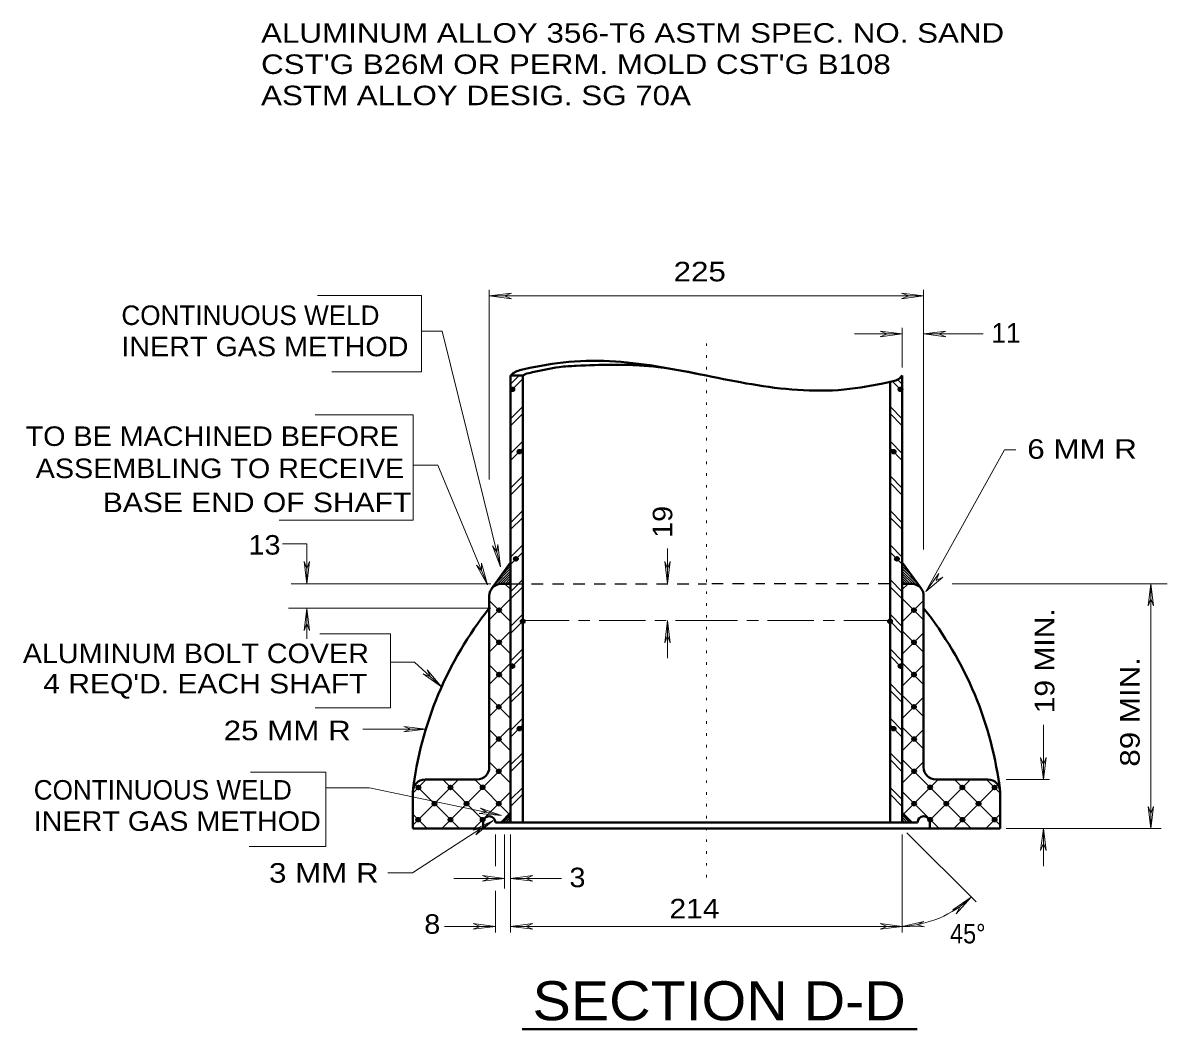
# Model space of a CAD drawing. Extents: x 312583 to 312854, y 144418 to 144597.
# Drawn here: x 312764.39 to 312808.95, y 144460.51 to 144499.71 of the extents above; entities that cross this region are included whole.
import ezdxf
from ezdxf.enums import TextEntityAlignment as Align

# ---------------------------------------------------------------- set-up
doc = ezdxf.new("R2010")
doc.units = 0
doc.header["$LTSCALE"] = 0.3
doc.header["$PDMODE"] = 32
doc.header["$PDSIZE"] = 0.15
for name, pattern in [('DOTTED', [1.5, 0.3, -1.2]), ('LONG_DASH_SHORT_DASH', [9.9, 6, -1.2, 1.5, -1.2]), ('SHORT_DASHED', [2.7, 1.5, -1.2])]:
    doc.linetypes.add(name, pattern=pattern)
doc.layers.add('1', color=7, linetype='Continuous', lineweight=35)

msp = doc.modelspace()

# ---------------------------------------------------------------- linework, layer by layer
at = {"layer": '1', "lineweight": 13}
for p, q in [((312775.8618, 144489.093), (312779.9183, 144489.093)), ((312779.9183, 144486.1193), (312779.9183, 144489.093)), ((312782.5566, 144481.9255), (312782.5566, 144489.3065)), ((312782.5566, 144489.0702), (312783.4182, 144489.1769)), ((312782.5566, 144489.0702), (312799.4688, 144489.0702)), ((312782.5566, 144489.0702), (312783.4182, 144488.9634)), ((312783.4182, 144489.1769), (312783.1437, 144489.0702)), ((312783.4182, 144488.9634), (312783.1437, 144489.0702)), ((312798.6148, 144489.1769), (312798.8893, 144489.0702)), ((312799.4688, 144489.0702), (312798.6148, 144489.1769)), ((312798.6148, 144488.9634), (312798.8893, 144489.0702)), ((312799.4688, 144489.0702), (312798.6148, 144488.9634)), ((312799.4688, 144479.1958), (312799.4688, 144489.3065)), ((312779.9183, 144487.6976), (312780.7189, 144487.6976)), ((312780.7189, 144487.6976), (312782.9912, 144478.5248)), ((312798.6377, 144487.5909), (312796.7848, 144487.5909)), ((312797.776, 144487.6976), (312798.0506, 144487.5909)), ((312798.6377, 144487.5909), (312797.776, 144487.6976)), ((312797.776, 144487.4842), (312798.0506, 144487.5909)), ((312798.6377, 144487.5909), (312797.776, 144487.4842)), ((312798.6377, 144486.2794), (312798.6377, 144487.8273)), ((312799.4764, 144487.5909), (312800.338, 144487.6976)), ((312799.4764, 144487.5909), (312801.7944, 144487.5909)), ((312799.4764, 144487.5909), (312800.338, 144487.4842)), ((312800.338, 144487.6976), (312800.0636, 144487.5909)), ((312800.338, 144487.4842), (312800.0636, 144487.5909)), ((312776.426, 144486.1193), (312779.9183, 144486.1193)), ((312783.3877, 144485.6313), (312783.7232, 144485.9668)), ((312783.3877, 144485.3644), (312783.868, 144485.8372)), ((312798.6377, 144485.6313), (312798.4394, 144485.8295)), ((312798.6377, 144485.3644), (312798.2717, 144485.7304)), ((312775.7703, 144484.4418), (312779.5904, 144484.4418)), ((312779.5904, 144480.3395), (312779.5904, 144484.4418)), ((312783.3877, 144484.2816), (312783.868, 144484.762)), ((312783.3877, 144484.0148), (312783.868, 144484.4875)), ((312798.6377, 144484.2816), (312798.1649, 144484.762)), ((312798.6377, 144484.0148), (312798.1649, 144484.4875)), ((312783.3877, 144482.932), (312783.868, 144483.4124)), ((312783.3877, 144482.6652), (312783.868, 144483.1455)), ((312798.6377, 144482.932), (312798.1649, 144483.4124)), ((312798.6377, 144482.6652), (312798.1649, 144483.1455)), ((312799.5527, 144477.5564), (312802.6215, 144483.0727)), ((312802.6215, 144483.0727), (312803.0638, 144483.0727)), ((312779.5904, 144482.4822), (312780.5588, 144482.4822)), ((312780.5588, 144482.4822), (312782.4803, 144477.8233)), ((312783.3877, 144481.59), (312783.868, 144482.0628)), ((312783.3877, 144481.3155), (312783.868, 144481.7959)), ((312798.6377, 144481.59), (312798.1649, 144482.0628)), ((312798.6377, 144481.3155), (312798.1649, 144481.7959)), ((312783.3877, 144480.2404), (312783.868, 144480.7208)), ((312783.3877, 144479.9735), (312783.868, 144480.4463)), ((312798.6377, 144480.2404), (312798.1649, 144480.7208)), ((312798.6377, 144479.9735), (312798.1649, 144480.4463)), ((312774.3749, 144480.3395), (312779.5904, 144480.3395)), ((312774.4969, 144479.4169), (312775.45, 144479.4169)), ((312775.45, 144477.8614), (312775.45, 144479.4169)), ((312782.6786, 144479.333), (312782.8463, 144479.0966)), ((312782.9912, 144478.5248), (312782.6786, 144479.333)), ((312782.8844, 144479.3864), (312782.8463, 144479.0966)), ((312782.9912, 144478.5248), (312782.8844, 144479.3864)), ((312783.3877, 144478.8908), (312783.868, 144479.3712)), ((312783.3877, 144478.6163), (312783.868, 144479.0966)), ((312789.4953, 144477.8614), (312789.4953, 144479.2339)), ((312798.6377, 144478.8908), (312798.1649, 144479.3712)), ((312798.6453, 144478.6163), (312798.1649, 144479.0966)), ((312775.3433, 144478.723), (312775.45, 144478.4485)), ((312775.45, 144477.8614), (312775.3433, 144478.723)), ((312775.5568, 144478.723), (312775.45, 144478.4485)), ((312775.45, 144477.8614), (312775.5568, 144478.723)), ((312782.2516, 144478.662), (312782.2516, 144478.3723)), ((312782.4803, 144477.8233), (312782.2516, 144478.662)), ((312789.3886, 144478.723), (312789.4953, 144478.4485)), ((312789.4953, 144477.8614), (312789.3886, 144478.723)), ((312789.602, 144478.723), (312789.4953, 144478.4485)), ((312789.4953, 144477.8614), (312789.602, 144478.723)), ((312782.0533, 144478.5858), (312782.2516, 144478.3723)), ((312782.4803, 144477.8233), (312782.0533, 144478.5858)), ((312799.5527, 144477.5564), (312800.0636, 144478.2579)), ((312800.0636, 144478.2579), (312799.9568, 144477.9834)), ((312782.6176, 144477.8614), (312774.84, 144477.8614)), ((312783.3953, 144477.6326), (312783.1666, 144477.8614)), ((312783.3877, 144477.5412), (312783.868, 144478.0215)), ((312798.6377, 144477.5412), (312798.1649, 144478.0215)), ((312798.6377, 144477.6326), (312798.8664, 144477.8614)), ((312799.5527, 144477.5564), (312800.216, 144478.113)), ((312800.216, 144478.113), (312799.9568, 144477.9834)), ((312808.9543, 144477.8614), (312800.582, 144477.8614)), ((312808.3214, 144477.8614), (312808.2147, 144476.9998)), ((312808.3214, 144468.3302), (312808.3214, 144477.8614)), ((312808.3214, 144477.8614), (312808.4282, 144476.9998)), ((312783.3877, 144477.2743), (312783.868, 144477.747)), ((312798.6377, 144477.2743), (312798.1649, 144477.747)), ((312782.6176, 144476.9083), (312774.7409, 144476.9083)), ((312775.45, 144476.9006), (312775.3433, 144476.039)), ((312775.45, 144475.7188), (312775.45, 144476.9006)), ((312775.45, 144476.9006), (312775.5568, 144476.039)), ((312782.5566, 144476.4508), (312783.3953, 144477.2895)), ((312783.3953, 144476.3745), (312782.5566, 144477.2133)), ((312799.4688, 144476.4508), (312798.6377, 144477.2895)), ((312798.6377, 144476.3745), (312799.4688, 144477.2133)), ((312808.2147, 144476.9998), (312808.3214, 144477.2743)), ((312808.4282, 144476.9998), (312808.3214, 144477.2743)), ((312783.3877, 144476.1915), (312783.868, 144476.6719)), ((312789.4953, 144476.4355), (312789.3886, 144475.5663)), ((312789.4953, 144474.9639), (312789.4953, 144476.4355)), ((312789.4953, 144476.4355), (312789.602, 144475.5663)), ((312798.6377, 144476.1915), (312798.1649, 144476.6719)), ((312775.3433, 144476.039), (312775.45, 144476.3135)), ((312775.5568, 144476.039), (312775.45, 144476.3135)), ((312782.5566, 144475.2003), (312783.3953, 144476.0314)), ((312783.3877, 144475.9246), (312783.868, 144476.405)), ((312798.6377, 144475.9246), (312798.1649, 144476.405)), ((312799.4688, 144475.2003), (312798.6377, 144476.0314)), ((312775.9533, 144475.917), (312778.7059, 144475.917)), ((312783.3953, 144475.124), (312782.5566, 144475.9552)), ((312789.3886, 144475.5663), (312789.4953, 144475.8408)), ((312789.602, 144475.5663), (312789.4953, 144475.8408)), ((312798.6377, 144475.124), (312799.4688, 144475.9552)), ((312783.3877, 144474.8495), (312783.868, 144475.3223)), ((312798.6377, 144474.8495), (312798.1649, 144475.3223)), ((312782.5566, 144473.9422), (312783.3953, 144474.7809)), ((312783.3953, 144473.8659), (312782.5566, 144474.697)), ((312783.3877, 144474.575), (312783.868, 144475.0554)), ((312798.6377, 144474.575), (312798.1649, 144475.0554)), ((312799.4688, 144473.9422), (312798.6377, 144474.7809)), ((312798.6377, 144473.8659), (312799.4688, 144474.697)), ((312779.9869, 144474.3463), (312780.2614, 144474.2395)), ((312780.696, 144473.8506), (312779.9869, 144474.3463)), ((312780.1318, 144474.5064), (312780.2614, 144474.2395)), ((312780.696, 144473.8506), (312780.1318, 144474.5064)), ((312783.3953, 144473.4999), (312783.868, 144473.9803)), ((312798.6377, 144473.4999), (312798.1649, 144473.9803)), ((312782.5566, 144472.6916), (312783.3953, 144473.5228)), ((312783.3877, 144472.6078), (312782.5566, 144473.4465)), ((312783.3877, 144473.233), (312783.868, 144473.7058)), ((312798.6377, 144473.233), (312798.1649, 144473.7058)), ((312799.4688, 144472.6916), (312798.6377, 144473.5228)), ((312798.6377, 144472.6078), (312799.4688, 144473.4465)), ((312783.3877, 144472.1503), (312783.868, 144472.6306)), ((312798.6377, 144472.1503), (312798.1649, 144472.6306)), ((312777.6338, 144472.196), (312780.086, 144472.196)), ((312779.2244, 144472.3028), (312779.4989, 144472.196)), ((312780.086, 144472.196), (312779.2244, 144472.3028)), ((312779.2244, 144472.0893), (312779.4989, 144472.196)), ((312780.086, 144472.196), (312779.2244, 144472.0893)), ((312782.5566, 144471.4335), (312783.3877, 144472.2723)), ((312783.3877, 144471.3573), (312782.5566, 144472.1884)), ((312783.3877, 144471.8834), (312783.868, 144472.3638)), ((312798.6377, 144471.8834), (312798.1649, 144472.3638)), ((312799.4688, 144471.4335), (312798.6377, 144472.2723)), ((312798.6377, 144471.3573), (312799.4688, 144472.1884)), ((312804.1353, 144470.2364), (312804.1353, 144472.3615)), ((312783.3877, 144470.8083), (312783.868, 144471.281)), ((312798.6377, 144470.8083), (312798.1649, 144471.281)), ((312804.0286, 144471.098), (312804.1353, 144470.8235)), ((312804.1353, 144470.2364), (312804.0286, 144471.098)), ((312804.242, 144471.098), (312804.1353, 144470.8235)), ((312804.1353, 144470.2364), (312804.242, 144471.098)), ((312780.7037, 144468.3302), (312783.3953, 144471.0218)), ((312783.3877, 144470.0992), (312782.5566, 144470.9303)), ((312783.3877, 144470.5338), (312783.868, 144471.0142)), ((312798.6377, 144470.5338), (312798.1649, 144471.0142)), ((312801.3293, 144468.3302), (312798.6377, 144471.0218)), ((312798.6377, 144470.0992), (312799.4688, 144470.9303)), ((312773.254, 144470.5185), (312776.1897, 144470.5185)), ((312776.1897, 144467.6286), (312776.1897, 144470.5185)), ((312779.5752, 144468.4598), (312781.3518, 144470.2364)), ((312779.5752, 144469.7103), (312780.1013, 144470.2364)), ((312782.3278, 144468.6428), (312780.7418, 144470.2364)), ((312783.3877, 144468.841), (312781.9923, 144470.2364)), ((312798.6377, 144468.841), (312800.033, 144470.2364)), ((312799.6976, 144468.6428), (312801.2912, 144470.2364)), ((312802.4502, 144468.4598), (312800.6736, 144470.2364)), ((312802.4502, 144469.7103), (312801.924, 144470.2364)), ((312802.6866, 144470.2364), (312804.3717, 144470.2364)), ((312776.1897, 144469.9085), (312777.89, 144469.9085)), ((312777.89, 144469.9085), (312783.0369, 144468.841)), ((312781.3899, 144468.3302), (312779.5752, 144470.1373)), ((312781.9542, 144468.3302), (312783.3953, 144469.7636)), ((312783.3877, 144469.4586), (312783.868, 144469.9314)), ((312798.6377, 144469.4586), (312798.1649, 144469.9314)), ((312800.0712, 144468.3302), (312798.6377, 144469.7636)), ((312800.643, 144468.3302), (312802.4502, 144470.1373)), ((312783.3877, 144469.1842), (312783.868, 144469.6645)), ((312798.6377, 144469.1842), (312798.1649, 144469.6645)), ((312780.1318, 144468.3302), (312779.5752, 144468.8868)), ((312782.1677, 144468.9096), (312782.4574, 144468.963)), ((312783.0369, 144468.841), (312782.1677, 144468.9096)), ((312782.2134, 144469.1155), (312782.4574, 144468.963)), ((312783.0369, 144468.841), (312782.2134, 144469.1155)), ((312801.8936, 144468.3302), (312802.4502, 144468.8868)), ((312808.2147, 144469.1918), (312808.3214, 144468.9173)), ((312808.3214, 144468.3302), (312808.2147, 144469.1918)), ((312808.4282, 144469.1918), (312808.3214, 144468.9173)), ((312808.3214, 144468.3302), (312808.4282, 144469.1918)), ((312782.709, 144468.6428), (312779.5599, 144466.6069)), ((312782.709, 144468.6428), (312781.9237, 144468.2692)), ((312782.709, 144468.6428), (312782.038, 144468.0862)), ((312783.8528, 144468.5665), (312783.868, 144468.5818)), ((312798.1802, 144468.5665), (312798.1649, 144468.5818)), ((312781.9237, 144468.2692), (312782.2134, 144468.3225)), ((312782.038, 144468.0862), (312782.2134, 144468.3225)), ((312782.7929, 144468.0938), (312782.7929, 144466.8585)), ((312783.1513, 144468.0938), (312783.1513, 144465.9969)), ((312783.3877, 144468.0938), (312783.3877, 144464.2813)), ((312798.6377, 144468.0938), (312798.6377, 144464.2813)), ((312798.813, 144468.1624), (312801.5123, 144465.4708)), ((312802.6866, 144468.3302), (312808.7256, 144468.3302)), ((312804.1353, 144468.3302), (312804.0286, 144467.4685)), ((312804.1353, 144466.8585), (312804.1353, 144468.3302)), ((312804.1353, 144468.3302), (312804.242, 144467.4685)), ((312773.2083, 144467.6286), (312776.1897, 144467.6286)), ((312804.0286, 144467.4685), (312804.1353, 144467.743)), ((312804.242, 144467.4685), (312804.1353, 144467.743)), ((312778.6068, 144466.6069), (312779.5599, 144466.6069)), ((312783.1513, 144466.3858), (312781.1764, 144466.3858)), ((312782.2897, 144466.4925), (312782.5642, 144466.3858)), ((312783.1513, 144466.3858), (312782.2897, 144466.4925)), ((312782.2897, 144466.279), (312782.5642, 144466.3858)), ((312783.1513, 144466.3858), (312782.2897, 144466.279)), ((312783.3877, 144466.3858), (312784.2493, 144466.4925)), ((312785.3626, 144466.3858), (312783.3877, 144466.3858)), ((312783.3877, 144466.3858), (312784.2493, 144466.279)), ((312784.2493, 144466.4925), (312783.9748, 144466.3858)), ((312784.2493, 144466.279), (312783.9748, 144466.3858)), ((312782.7929, 144465.9054), (312782.7929, 144464.2813)), ((312801.3293, 144465.6538), (312800.6049, 144465.1658)), ((312801.3293, 144465.6538), (312800.7422, 144465.0056)), ((312800.6049, 144465.1658), (312800.887, 144465.2649)), ((312800.7422, 144465.0056), (312800.887, 144465.2649)), ((312782.7929, 144464.5176), (312780.818, 144464.5176)), ((312781.9313, 144464.6244), (312782.2058, 144464.5176)), ((312782.7929, 144464.5176), (312781.9313, 144464.6244)), ((312781.9313, 144464.4109), (312782.2058, 144464.5176)), ((312782.7929, 144464.5176), (312781.9313, 144464.4109)), ((312783.3877, 144464.5176), (312784.2493, 144464.6244)), ((312783.3877, 144464.5176), (312798.6377, 144464.5176)), ((312783.3877, 144464.5176), (312784.2493, 144464.4109)), ((312784.2493, 144464.6244), (312783.9748, 144464.5176)), ((312784.2493, 144464.4109), (312783.9748, 144464.5176)), ((312797.776, 144464.6244), (312798.0506, 144464.5176)), ((312798.6377, 144464.5176), (312797.776, 144464.6244)), ((312797.776, 144464.4109), (312798.0506, 144464.5176)), ((312798.6377, 144464.5176), (312797.776, 144464.4109)), ((312798.6377, 144464.5176), (312799.484, 144464.7083)), ((312798.6377, 144464.5176), (312799.5069, 144464.4948)), ((312799.484, 144464.7083), (312799.2248, 144464.571)), ((312799.5069, 144464.4948), (312799.2248, 144464.571))]:
    msp.add_line(p, q, dxfattribs=at)
at = {"layer": '1', "linetype": 'DOTTED', "lineweight": 13}
msp.add_line((312791.0127, 144466.4239), (312791.0127, 144487.2706), dxfattribs=at)
at = {"layer": '1', "lineweight": 40}
for p, q in [((312783.3877, 144485.9668), (312783.3877, 144468.5665)), ((312783.868, 144485.9668), (312783.3877, 144485.9668)), ((312783.868, 144485.9668), (312783.868, 144468.5665)), ((312798.6377, 144485.9668), (312798.6377, 144468.5665)), ((312798.1649, 144485.7152), (312798.1649, 144468.5665)), ((312783.3877, 144478.6925), (312782.648, 144477.6632)), ((312798.6377, 144478.6925), (312799.3849, 144477.6632)), ((312783.0293, 144477.8614), (312783.3953, 144477.8614)), ((312798.996, 144477.8614), (312798.6377, 144477.8614)), ((312782.5566, 144477.381), (312782.5566, 144470.7168)), ((312799.4688, 144477.381), (312799.4688, 144470.7168)), ((312780.0556, 144470.2364), (312782.0838, 144470.2364)), ((312801.9774, 144470.2364), (312799.9492, 144470.2364)), ((312779.5752, 144469.756), (312779.5752, 144468.3302)), ((312802.4502, 144469.756), (312802.4502, 144468.3302)), ((312783.0217, 144468.5665), (312783.3877, 144468.9325)), ((312799.0113, 144468.5665), (312798.6377, 144468.9325)), ((312782.3202, 144468.5665), (312782.3202, 144468.3302)), ((312782.7929, 144468.5665), (312791.0127, 144468.5665)), ((312799.2324, 144468.5665), (312791.0127, 144468.5665)), ((312799.7128, 144468.5665), (312799.7128, 144468.3302)), ((312779.5752, 144468.3302), (312791.0127, 144468.3302)), ((312802.4502, 144468.3302), (312791.0127, 144468.3302)), ((312783.8353, 144460.5145), (312799.2201, 144460.5145))]:
    msp.add_line(p, q, dxfattribs=at)
at = {"layer": '1', "lineweight": 25}
for p, q in [((312783.258, 144478.5095), (312783.3877, 144478.6468)), ((312798.7749, 144478.5095), (312798.6377, 144478.6468)), ((312782.77, 144477.8385), (312783.3877, 144478.4562)), ((312782.8768, 144477.8462), (312783.3877, 144478.357)), ((312782.9759, 144477.8538), (312783.3877, 144478.2655)), ((312783.014, 144478.174), (312783.3877, 144478.5476)), ((312799.0113, 144478.174), (312798.6377, 144478.5476)), ((312799.2553, 144477.8385), (312798.6377, 144478.4562)), ((312799.1562, 144477.8462), (312798.6377, 144478.357)), ((312799.0494, 144477.8538), (312798.6377, 144478.2655)), ((312783.075, 144477.8614), (312783.3877, 144478.174)), ((312783.1742, 144477.8614), (312783.3877, 144478.0825)), ((312783.2657, 144477.8614), (312783.3877, 144477.9834)), ((312783.3648, 144477.8614), (312783.3877, 144477.8919)), ((312798.9503, 144477.8614), (312798.6377, 144478.174)), ((312798.8588, 144477.8614), (312798.6377, 144478.0825)), ((312798.7597, 144477.8614), (312798.6377, 144477.9834)), ((312798.6682, 144477.8614), (312798.6377, 144477.8919)), ((312783.1056, 144468.5665), (312783.3877, 144468.8563)), ((312798.9274, 144468.5665), (312798.6377, 144468.8563)), ((312783.197, 144468.5665), (312783.3877, 144468.7648)), ((312783.2886, 144468.5665), (312783.3877, 144468.6656)), ((312783.3877, 144468.5665), (312783.3877, 144468.5742)), ((312798.8283, 144468.5665), (312798.6377, 144468.7648)), ((312798.7368, 144468.5665), (312798.6377, 144468.6656)), ((312798.6453, 144468.5665), (312798.6377, 144468.5742))]:
    msp.add_line(p, q, dxfattribs=at)
at = {"layer": '1', "linetype": 'SHORT_DASHED', "lineweight": 25}
for p in [(312783.3953, 144477.8614), (312798.1497, 144477.8614)]:
    msp.add_line(p, (312791.0127, 144477.8614), dxfattribs=at)
at = {"layer": '1', "linetype": 'LONG_DASH_SHORT_DASH', "lineweight": 13}
for p in [(312783.868, 144476.4355), (312798.1649, 144476.4355)]:
    msp.add_line(p, (312791.0127, 144476.4355), dxfattribs=at)
at = {"layer": '1', "lineweight": 13}
for points in [[(312775.7703, 144473.0272), (312778.7059, 144473.0272), (312778.7059, 144475.917)], [(312778.7059, 144474.8038), (312779.6438, 144474.8038), (312780.696, 144473.8506)]]:
    msp.add_lwpolyline(points, dxfattribs=at)
at = {"layer": '1', "lineweight": 40}
for centre, radius, start, end in [((312783.0331, 144477.3848), 0.4766, 90, 180), ((312798.9961, 144477.3848), 0.4766, 0, 90), ((312793.6129, 144468.1048), 14.1331, 141.47211, 173.27514), ((312788.4162, 144468.1048), 14.1331, 6.72486, 38.52789), ((312782.08, 144470.713), 0.4766, 270, 0), ((312799.9492, 144470.713), 0.4766, 180, 270), ((312780.0536, 144469.7598), 0.4766, 90, 180), ((312801.9755, 144469.7598), 0.4766, 0, 90), ((312782.5565, 144468.5684), 0.2383, 0, 180), ((312799.4726, 144468.5684), 0.2383, 0, 180)]:
    msp.add_arc(centre, radius, start, end, dxfattribs=at)
at = {"layer": '1', "lineweight": 13}
msp.add_arc((312798.4607, 144468.6986), 4.1848, 272.45055, 313.23855, dxfattribs=at)
at = {"layer": '1', "lineweight": 40}
for points in [[(312783.3877, 144485.9668), (312783.4868, 144486.0583), (312783.9138, 144486.2184), (312785.6523, 144486.5005), (312787.467, 144486.5158), (312791.0127, 144485.9668)], [(312783.868, 144485.9668), (312783.9596, 144486.0202), (312784.234, 144486.0964), (312785.2787, 144486.3023), (312785.942, 144486.348), (312787.3603, 144486.3938), (312788.4126, 144486.3633), (312789.1369, 144486.3023), (312791.0127, 144485.9668)], [(312798.6377, 144485.9668), (312798.5386, 144485.8676), (312798.1116, 144485.7075), (312796.373, 144485.4254), (312794.5659, 144485.4102), (312791.0127, 144485.9668)]]:
    msp.add_spline(points, degree=3, dxfattribs=at)
at = {"layer": '1'}
for p in [(312783.4563, 144485.433), (312798.569, 144485.433), (312783.7308, 144483.0083), (312798.3022, 144483.0083), (312783.5936, 144478.8298), (312798.4318, 144478.8298), (312782.9378, 144476.832), (312799.0952, 144476.832), (312783.8604, 144476.3974), (312798.1649, 144476.3974), (312782.9378, 144475.5815), (312799.0952, 144475.5815), (312783.4563, 144474.6513), (312798.569, 144474.6513), (312782.9378, 144474.3234), (312799.0952, 144474.3234), (312782.9302, 144473.0653), (312799.0952, 144473.0653), (312783.7308, 144472.2189), (312798.3022, 144472.2189), (312782.9302, 144471.8148), (312799.1028, 144471.8148), (312782.9302, 144470.5566), (312799.1028, 144470.5566), (312779.7963, 144469.9238), (312781.0468, 144469.9238), (312782.2973, 144469.9314), (312799.728, 144469.9314), (312800.9786, 144469.9238), (312802.2367, 144469.9238), (312780.4216, 144469.2985), (312781.672, 144469.2985), (312782.9302, 144469.2985), (312799.1028, 144469.2985), (312800.3533, 144469.2985), (312801.6114, 144469.2985), (312779.7887, 144468.6733), (312781.0468, 144468.6733), (312782.2973, 144468.6733), (312799.728, 144468.6733), (312800.9862, 144468.6733), (312802.2367, 144468.6733)]:
    msp.add_point(p, dxfattribs=at)

# ---------------------------------------------------------------- texts
for s, width, p in [('ALUMINUM ALLOY 356-T6 ASTM SPEC. NO. SAND', 1.2, (312773.6692, 144498.9355)), ("CST'G B26M OR PERM. MOLD CST'G B108", 1.2, (312773.6692, 144497.718)), ('ASTM ALLOY DESIG. SG 70A', 1.2, (312773.6692, 144496.5005)), ('225 ', 1.2, (312789.7351, 144489.6412)), ('INERT GAS METHOD', 1.1, (312768.2292, 144486.7217)), ('TO BE MACHINED BEFORE', 1.1, (312764.4993, 144483.2298)), ('6 MM R', 1.2, (312803.5082, 144482.7283)), ('ASSEMBLING TO RECEIVE', 1.1, (312764.8934, 144481.9765)), ('BASE END OF SHAFT', 1.15, (312767.5046, 144480.6498)), ('13 ', 1.1, (312773.1812, 144478.9966)), ('ALUMINUM BOLT COVER', 1.1, (312764.3902, 144474.7703)), ("4 REQ'D. EACH SHAFT", 1.15, (312765.186, 144473.5918)), ('25 MM R', 1.2, (312772.2127, 144471.7667)), ('INERT GAS METHOD', 1.1, (312764.8152, 144468.236)), ('3 MM R', 1.2, (312773.9792, 144466.2185)), ('3 ', 1.1, (312785.6785, 144466.0418)), ('214 ', 1.15, (312789.5727, 144464.8289)), ('8 ', 1.1, (312780.0239, 144464.2284)), ('45°', 0.9, (312800.4995, 144463.8527))]:
    msp.add_text(s, height=0.76, dxfattribs=dict(at, width=width)).set_placement(p)
for s, p in [('CONTINUOUS WELD', (312768.2292, 144487.9392)), ('11 ', (312802.114, 144487.2532)), ('CONTINUOUS WELD', (312764.8152, 144469.4535))]:
    msp.add_text(s, height=0.76, dxfattribs=at).set_placement(p)
for s, width, p in [('19 ', 1.1, (312789.6826, 144479.6493)), ('19 MIN.', 1.15, (312804.5615, 144472.8146)), ('89 MIN.', 1.2, (312807.8854, 144470.7381))]:
    msp.add_text(s, height=0.76, rotation=90, dxfattribs=dict(at, width=width)).set_placement(p)
at = {"layer": '1', "width": 1.1}
msp.add_text('SECTION D-D', height=1.52, dxfattribs=at).set_placement((312791.507, 144460.8595), align=Align.CENTER)

doc.saveas('drawing.dxf')
